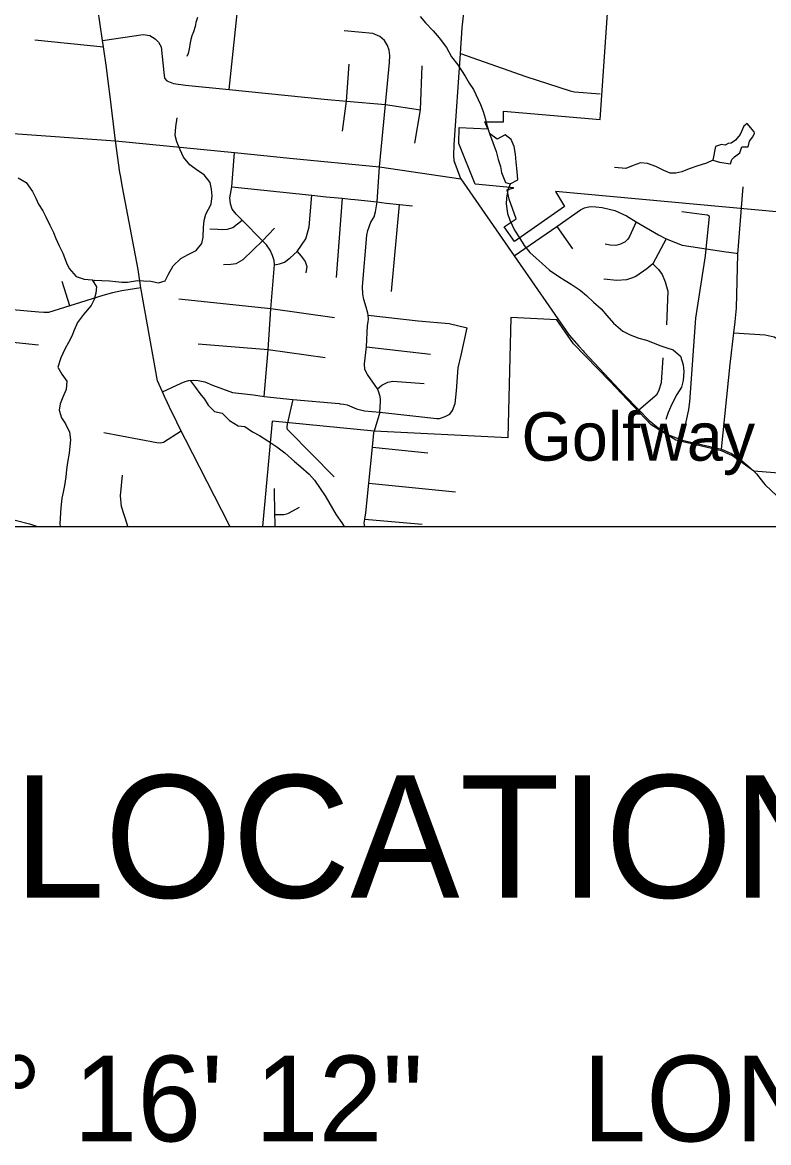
# Model space of a CAD drawing. Extents: x 0 to 69.5, y -4.5 to 22.
# Drawn here: x 4.384 to 5.602, y 13.194 to 15.023 of the extents above; entities that cross this region are included whole.
import ezdxf

# ---------------------------------------------------------------- set-up
doc = ezdxf.new("R2010")
doc.units = 0
for name, color, linetype in [('GM_X_City_Street', 7, 'Continuous'), ('GM_X_Corporation', 7, 'Continuous'), ('GM_X_County_Road', 7, 'Continuous'), ('GM_X_Minor_Lake', 7, 'Continuous'), ('GM_X_Minor_River', 7, 'Continuous'), ('GM_X_Township_ROW', 7, 'Continuous'), ('GM_X_Township_Subdivision', 7, 'Continuous'), ('GM_X_Unincorporated_Text', 7, 'Continuous'), ('GM_X_US_Route', 7, 'Continuous'), ('SH_Data', 7, 'Continuous')]:
    doc.layers.add(name, color=color, linetype=linetype)

msp = doc.modelspace()

# ---------------------------------------------------------------- linework, layer by layer
at = {"layer": 'GM_X_City_Street'}
for points in [[(4.8158, 14.3669), (4.8153, 14.3623), (4.8153, 14.3613), (4.8154, 14.3604), (4.8157, 14.3594), (4.816, 14.3588), (4.8185, 14.356), (4.8927, 14.2811)], [(4.9426, 14.2), (4.9417, 14.2051), (4.9428, 14.212), (4.9443, 14.222), (4.9492, 14.2708), (4.9551, 14.3294), (4.9574, 14.353), (4.9577, 14.3554)], [(4.9551, 14.3294), (5.0453, 14.3199)], [(4.9492, 14.2708), (5.0904, 14.2564)], [(5.5934, 14.2713), (5.5961, 14.2678), (5.6155, 14.2498), (5.6358, 14.2115), (5.6405, 14.2)], [(4.7969, 14.2), (4.7964, 14.2007), (4.7962, 14.2064), (4.7959, 14.2197), (4.7949, 14.2619)], [(4.7959, 14.2197), (4.8102, 14.2197), (4.8151, 14.2207), (4.8182, 14.2214), (4.825, 14.2254), (4.8359, 14.2316)], [(4.9428, 14.212), (5.0363, 14.2035)]]:
    msp.add_lwpolyline(points, dxfattribs=at)
at = {"layer": 'GM_X_Corporation'}
msp.add_line((4.7755, 14.2), (7.1307, 14.2), dxfattribs=at)
for points in [[(6.9956, 14.8531), (6.7125, 14.887), (6.701, 14.6468), (6.473, 14.6817), (6.4728, 14.6434), (5.9933, 14.679), (5.254, 14.7467), (5.2688, 14.7224), (5.187, 14.6653), (5.1701, 14.6893), (5.1899, 14.7022), (5.1782, 14.7342), (5.1751, 14.7498), (5.1856, 14.7529), (5.1229, 14.7587), (5.0962, 14.8253), (5.0967, 14.8513), (5.1434, 14.8494), (5.1387, 14.8608), (5.1692, 14.8604), (5.1692, 14.8783), (5.3269, 14.8644), (5.36, 15.3466)], [(6.9956, 14.8531), (6.7125, 14.887), (6.701, 14.6468), (6.473, 14.6817), (6.4728, 14.6434), (5.9933, 14.679), (5.9556, 14.2595), (5.5778, 14.2901), (5.5429, 14.3154), (5.5247, 14.3232), (5.4502, 14.341), (5.4099, 14.3661), (5.3427, 14.4372), (5.2834, 14.4983), (5.256, 14.5372), (5.1809, 14.5414), (5.1758, 14.3448), (4.9577, 14.3554), (4.7915, 14.3718), (4.7755, 14.2)]]:
    msp.add_lwpolyline(points, dxfattribs=at)
at = {"layer": 'GM_X_County_Road'}
for points in [[(5.0993, 14.7678), (5.0886, 14.7969), (5.0877, 14.8064), (5.0885, 14.8231), (5.0988, 14.9724), (5.1017, 15.0142), (5.1101, 15.0924)], [(4.0583, 14.9068), (4.0642, 14.9062), (4.1976, 14.8897), (4.2818, 14.8811), (4.2881, 14.8783), (4.2964, 14.8747), (4.3359, 14.8464), (4.3446, 14.8435), (4.3609, 14.8419), (4.5356, 14.8298)], [(4.5356, 14.8298), (4.7297, 14.8106), (4.8202, 14.8014), (4.9663, 14.7871), (5.0993, 14.7678)], [(5.0993, 14.7678), (5.1865, 14.6418), (5.2762, 14.5124), (5.2922, 14.4942), (5.2988, 14.4868)], [(5.2988, 14.4868), (5.3005, 14.4848), (5.3666, 14.4142), (5.39, 14.3902), (5.4068, 14.3731), (5.4213, 14.3611), (5.4388, 14.3493), (5.4588, 14.3415), (5.4609, 14.341), (5.525, 14.3259), (5.5412, 14.3193), (5.5527, 14.3119), (5.56, 14.306), (5.5714, 14.2962), (5.5823, 14.2858), (5.5934, 14.2713)], [(4.1028, 14.434), (4.1195, 14.4158), (4.1579, 14.3722), (4.1966, 14.328), (4.2251, 14.2968), (4.2366, 14.285), (4.2423, 14.2793), (4.2507, 14.2724), (4.2769, 14.2535), (4.3069, 14.2332), (4.3221, 14.2249), (4.3341, 14.2204), (4.3524, 14.2153), (4.3953, 14.2041), (4.4082, 14.2)]]:
    msp.add_lwpolyline(points, dxfattribs=at)
at = {"layer": 'GM_X_Minor_Lake'}
for points in [[(5.5107, 14.7981), (5.5218, 14.7946), (5.5395, 14.7919), (5.542, 14.7991), (5.5463, 14.8035), (5.5551, 14.8102), (5.558, 14.82), (5.5687, 14.8198), (5.5708, 14.8288), (5.5759, 14.8363), (5.579, 14.8419), (5.5783, 14.8442), (5.5668, 14.8581), (5.5614, 14.8537), (5.5554, 14.8402), (5.548, 14.8308), (5.5407, 14.8257), (5.5357, 14.825), (5.5311, 14.8225), (5.5247, 14.8238), (5.5151, 14.8202)], [(5.1462, 14.8416), (5.1569, 14.812), (5.1604, 14.799), (5.1639, 14.7875), (5.1659, 14.778), (5.172, 14.7618), (5.1796, 14.7594)], [(5.1796, 14.7594), (5.1926, 14.7659), (5.1914, 14.7796), (5.1895, 14.7945), (5.1883, 14.8078), (5.1864, 14.8201), (5.1817, 14.832), (5.1716, 14.8394), (5.1585, 14.8325), (5.1462, 14.8416)], [(5.5151, 14.8202), (5.5107, 14.7981)]]:
    msp.add_lwpolyline(points, dxfattribs=at)
at = {"layer": 'GM_X_Minor_River'}
for points in [[(4.6696, 15.0309), (4.6667, 15.0226), (4.6654, 15.0162), (4.6628, 15.0075), (4.6604, 15.0011), (4.6583, 14.995), (4.657, 14.9871), (4.6565, 14.9825), (4.6552, 14.9772), (4.6539, 14.9723), (4.6519, 14.9674)], [(5.0331, 15.0326), (5.0415, 15.0221), (5.0541, 15.0092), (5.0641, 14.9976), (5.0759, 14.9821), (5.0843, 14.967), (5.0946, 14.9535), (5.1063, 14.935), (5.1129, 14.9238), (5.1198, 14.9133), (5.1314, 14.8887), (5.1357, 14.8776), (5.1388, 14.8665), (5.142, 14.855), (5.1462, 14.8416)], [(4.4991, 14.6003), (4.502, 14.6021), (4.513, 14.6018), (4.5255, 14.6011), (4.5358, 14.6001), (4.5456, 14.5991), (4.5551, 14.5989), (4.5715, 14.6015), (4.581, 14.6009), (4.5931, 14.6006), (4.6056, 14.598), (4.6167, 14.6008), (4.6219, 14.6117), (4.6295, 14.6256), (4.6419, 14.6374), (4.6542, 14.644), (4.6673, 14.6505), (4.6767, 14.6617), (4.6789, 14.6723), (4.6792, 14.6879), (4.6803, 14.6993), (4.6832, 14.7098), (4.6916, 14.726), (4.6931, 14.74), (4.6922, 14.7507), (4.6902, 14.7618), (4.6802, 14.7742), (4.6693, 14.7809), (4.657, 14.7903), (4.6467, 14.8031), (4.6413, 14.815), (4.6355, 14.8281), (4.6327, 14.8385), (4.6338, 14.8525), (4.6361, 14.8673)], [(5.5107, 14.7981), (5.5003, 14.793), (5.4846, 14.7881), (5.472, 14.7838), (5.4601, 14.7792), (5.4505, 14.7767), (5.441, 14.777), (5.4305, 14.7814), (5.4178, 14.7878), (5.4042, 14.7927), (5.3928, 14.7937), (5.3806, 14.7895), (5.3687, 14.7844), (5.3501, 14.786)], [(4.3768, 14.7694), (4.3896, 14.7615), (4.4002, 14.7471), (4.4053, 14.736), (4.41, 14.7264), (4.4169, 14.7152), (4.422, 14.7055), (4.4285, 14.6917), (4.4343, 14.6801), (4.4383, 14.6702), (4.4437, 14.6582), (4.4495, 14.6463), (4.4555, 14.6306), (4.4599, 14.621), (4.4713, 14.6081), (4.4845, 14.604), (4.4974, 14.6029), (4.5047, 14.591), (4.5034, 14.5811), (4.5008, 14.5705), (4.496, 14.5607), (4.4835, 14.5462), (4.4733, 14.5328), (4.4681, 14.5207), (4.464, 14.5106), (4.4585, 14.5001), (4.4529, 14.4892), (4.4461, 14.4753), (4.4412, 14.4602), (4.4481, 14.4486), (4.4558, 14.437), (4.4551, 14.4237), (4.4495, 14.4113), (4.4454, 14.4), (4.4436, 14.3901), (4.4471, 14.3771), (4.4541, 14.3675), (4.4606, 14.354), (4.4618, 14.3414), (4.4612, 14.3308), (4.4598, 14.3194), (4.4571, 14.3046), (4.4553, 14.2929), (4.4543, 14.2811), (4.452, 14.2667), (4.4499, 14.2561), (4.4481, 14.2463), (4.4462, 14.2304), (4.4451, 14.2137), (4.4448, 14.2042), (4.4449, 14.2)], [(5.1805, 14.7599), (5.1763, 14.7496), (5.1737, 14.7359), (5.1731, 14.7265), (5.1757, 14.7112), (5.1793, 14.7001), (5.1868, 14.6839), (5.1949, 14.6712), (5.2026, 14.6588), (5.2118, 14.6472), (5.2222, 14.6378), (5.2319, 14.6292), (5.2442, 14.6186), (5.2595, 14.608), (5.2696, 14.6013), (5.2793, 14.5953), (5.2939, 14.5859), (5.3043, 14.5772), (5.3159, 14.5663), (5.3285, 14.5554), (5.3377, 14.5445), (5.3485, 14.532), (5.3637, 14.5187), (5.3757, 14.5128), (5.39, 14.5075), (5.4025, 14.5041), (5.4123, 14.5005), (5.4243, 14.4952), (5.4341, 14.4919), (5.4462, 14.4886), (5.4581, 14.478), (5.4623, 14.4639), (5.4636, 14.4528), (5.4625, 14.4384), (5.4595, 14.4274), (5.452, 14.4154), (5.4437, 14.3997), (5.438, 14.3858), (5.4339, 14.3744)], [(4.658, 14.4378), (4.6661, 14.4269), (4.6731, 14.4173), (4.6808, 14.4076), (4.6867, 14.3979), (4.6974, 14.3878), (4.7095, 14.3852), (4.7214, 14.3731), (4.736, 14.364), (4.7466, 14.3634), (4.7593, 14.3543), (4.7706, 14.3484), (4.784, 14.3397), (4.799, 14.3302), (4.8117, 14.32), (4.8277, 14.3059), (4.8381, 14.2973), (4.8519, 14.2855), (4.8604, 14.2758), (4.8699, 14.2619), (4.878, 14.2499), (4.8838, 14.2395), (4.89, 14.2291), (4.8959, 14.2191), (4.9051, 14.2059), (4.9086, 14.2)]]:
    msp.add_lwpolyline(points, dxfattribs=at)
at = {"layer": 'GM_X_Township_ROW'}
msp.add_lwpolyline([(5.5514, 14.6447), (5.5601, 14.7544)], dxfattribs=at)
at = {"layer": 'GM_X_Township_Subdivision'}
for points in [[(4.7213, 14.9134), (4.7368, 15.0634)], [(4.5144, 14.9937), (4.5806, 15.0034), (4.5916, 15.0014), (4.6001, 14.9964), (4.6058, 14.9909), (4.6098, 14.9829), (4.6143, 14.9412), (4.6153, 14.9319), (4.6193, 14.9277), (4.6303, 14.9232), (4.6496, 14.9204), (4.7213, 14.9134), (4.8763, 14.8977), (4.9125, 14.8942), (4.9763, 14.8887), (5.0335, 14.8802)], [(4.948, 14.5339), (4.9486, 14.5383), (4.948, 14.5448), (4.9477, 14.5482), (4.9445, 14.5578), (4.9411, 14.5708), (4.9394, 14.5792), (4.9386, 14.5918), (4.946, 14.6755), (4.9477, 14.6834), (4.9522, 14.697), (4.9577, 14.7057), (4.9601, 14.7136), (4.9629, 14.7298), (4.9636, 14.7466), (4.9663, 14.7871), (4.9763, 14.8887), (4.9828, 14.9574), (4.9835, 14.9691), (4.9823, 14.9779), (4.9798, 14.9851), (4.9748, 14.9936), (4.9673, 15.0001), (4.9558, 15.0046), (4.909, 15.0094)], [(4.4039, 14.9946), (4.5159, 14.9833)], [(5.0988, 14.9724), (5.2052, 14.9349), (5.2778, 14.9111), (5.285, 14.9094), (5.3266, 14.9065)], [(4.9062, 14.8455), (4.9125, 14.8942), (4.9168, 14.9549)], [(5.0241, 14.8259), (5.0335, 14.8802), (5.0364, 14.952)], [(4.778, 14.4122), (4.7846, 14.4883), (4.7893, 14.5551), (4.7949, 14.6269), (4.7948, 14.6341), (4.792, 14.6426), (4.7882, 14.6512), (4.7823, 14.6597), (4.7757, 14.6663), (4.7423, 14.7), (4.7327, 14.71), (4.7259, 14.7182), (4.7235, 14.7265), (4.722, 14.7368), (4.7257, 14.7543), (4.7297, 14.8106)], [(4.7257, 14.7543), (4.8558, 14.741), (4.8793, 14.7383), (4.9056, 14.7358), (4.919, 14.7346)], [(4.7949, 14.6269), (4.8031, 14.6288), (4.8116, 14.6317), (4.8207, 14.6384), (4.832, 14.649), (4.8462, 14.6696), (4.8487, 14.6772), (4.8517, 14.6892), (4.8558, 14.741)], [(4.9056, 14.7358), (4.8956, 14.6064)], [(4.919, 14.7346), (4.9262, 14.734), (4.9629, 14.7298), (4.9698, 14.729)], [(4.9698, 14.729), (4.978, 14.728), (4.999, 14.7254), (5.0206, 14.7234)], [(4.9862, 14.5837), (4.999, 14.7254)], [(5.1865, 14.6418), (5.2558, 14.6899), (5.2945, 14.7171), (5.3011, 14.7201), (5.3058, 14.7213), (5.3112, 14.7226)], [(5.3112, 14.7226), (5.32, 14.7219), (5.3302, 14.721), (5.3507, 14.7158), (5.37, 14.7072), (5.3858, 14.6971), (5.4218, 14.676), (5.4348, 14.6698), (5.4605, 14.6593), (5.4997, 14.6534), (5.5325, 14.6485), (5.5411, 14.6473), (5.5489, 14.6463), (5.5505, 14.6455), (5.5512, 14.6449), (5.5514, 14.6447)], [(5.4609, 14.341), (5.4694, 14.3808), (5.4714, 14.3907), (5.4731, 14.4032), (5.4832, 14.5398), (5.499, 14.6416), (5.4997, 14.6534), (5.5052, 14.706), (5.5018, 14.7085), (5.4927, 14.7092), (5.4604, 14.7136)], [(4.6894, 14.686), (4.7028, 14.6851), (4.7103, 14.6848), (4.7182, 14.6854), (4.7272, 14.6882), (4.7423, 14.7)], [(5.2558, 14.6899), (5.2816, 14.6534)], [(5.3858, 14.6971), (5.3746, 14.6735), (5.3718, 14.669), (5.3676, 14.6645), (5.36, 14.6608), (5.3524, 14.6588), (5.3434, 14.6592), (5.3348, 14.661)], [(4.7116, 14.6275), (4.7239, 14.628), (4.7326, 14.6291), (4.744, 14.6361), (4.7757, 14.6663), (4.7952, 14.6868)], [(5.4348, 14.6698), (5.4127, 14.6288), (5.4032, 14.6206), (5.3849, 14.6082), (5.378, 14.6052), (5.3697, 14.6025), (5.3541, 14.6013), (5.3326, 14.6035)], [(4.832, 14.649), (4.8388, 14.6411), (4.8454, 14.6326), (4.8478, 14.6244), (4.8465, 14.6139)], [(5.547, 14.5345), (5.5494, 14.5562), (5.5514, 14.6447)], [(5.4127, 14.6288), (5.4218, 14.6196), (5.4282, 14.6111), (5.4331, 14.5995), (5.4372, 14.5843), (5.4352, 14.5291)], [(4.4611, 14.5601), (4.4485, 14.6001)], [(4.5769, 14.5898), (4.5457, 14.5846), (4.5306, 14.5813), (4.5149, 14.5768), (4.4611, 14.5601), (4.426, 14.5494), (4.4187, 14.5494), (4.4102, 14.5498), (4.3675, 14.5534)], [(4.8929, 14.5405), (4.7893, 14.5551), (4.6387, 14.5711)], [(4.948, 14.5448), (5.0294, 14.5356), (5.0801, 14.5313), (5.1095, 14.5245)], [(4.4097, 14.496), (4.3628, 14.5007), (4.2815, 14.5075), (4.2152, 14.5138), (4.1302, 14.5211), (4.067, 14.5266), (4.0606, 14.5267), (4.0536, 14.5259), (4.0449, 14.5223), (4.033, 14.5098)], [(4.9024, 14.4004), (4.9077, 14.3994), (4.9135, 14.3983), (4.9291, 14.3918), (4.9422, 14.389), (4.9668, 14.3867), (5.0602, 14.3763), (5.0644, 14.3764), (5.074, 14.3794), (5.0815, 14.3832), (5.0858, 14.3891), (5.0899, 14.4005), (5.0923, 14.4215), (5.095, 14.4587), (5.0997, 14.4795), (5.1095, 14.5245)], [(4.9668, 14.3867), (4.9683, 14.4033), (4.9682, 14.4071), (4.9675, 14.4123), (4.9666, 14.4154), (4.9653, 14.4194), (4.9635, 14.4249), (4.9468, 14.4478), (4.9425, 14.4564), (4.9418, 14.4653), (4.9455, 14.4933), (4.9471, 14.5281), (4.948, 14.5339)], [(5.525, 14.3259), (5.5393, 14.4652), (5.545, 14.5162), (5.547, 14.5343), (5.547, 14.5345)], [(5.545, 14.5162), (5.5961, 14.5129), (5.6111, 14.5096), (5.6215, 14.5038), (5.6286, 14.494), (5.6354, 14.4771), (5.6429, 14.4654), (5.6507, 14.4615), (5.6608, 14.4589), (5.6803, 14.4563), (5.7698, 14.4494)], [(4.878, 14.4751), (4.7846, 14.4883), (4.6702, 14.4974)], [(4.9455, 14.4933), (5.05, 14.4811)], [(5.39, 14.3902), (5.4197, 14.416), (5.4234, 14.4231), (5.4269, 14.435), (5.4294, 14.4752)], [(4.6123, 14.4199), (4.6428, 14.4339), (4.6493, 14.4367), (4.6552, 14.4383), (4.6622, 14.4387), (4.6703, 14.4383), (4.6813, 14.4359), (4.6938, 14.4304), (4.7264, 14.4188), (4.7606, 14.4149), (4.778, 14.4122), (4.8252, 14.4072), (4.9008, 14.4007), (4.9024, 14.4004)], [(4.9635, 14.4249), (4.9701, 14.4308), (4.98, 14.4353), (4.9884, 14.437), (5.0392, 14.4331)], [(4.8252, 14.4072), (4.8158, 14.3669)], [(4.9668, 14.3867), (4.9577, 14.3554)], [(4.6428, 14.3557), (4.614, 14.3373), (4.6082, 14.336), (4.603, 14.3367), (4.5162, 14.3529)], [(4.5558, 14.2), (4.5545, 14.2035), (4.5454, 14.2324), (4.5434, 14.2501), (4.5471, 14.2836)]]:
    msp.add_lwpolyline(points, dxfattribs=at)
at = {"layer": 'GM_X_US_Route'}
for points in [[(4.5242, 14.9225), (4.5208, 14.9494), (4.5159, 14.9833), (4.5144, 14.9937), (4.4954, 15.1244), (4.4862, 15.1877), (4.4752, 15.2718), (4.4644, 15.355), (4.4625, 15.3694), (4.4601, 15.3824), (4.4536, 15.436), (4.4509, 15.4477), (4.4494, 15.4539)], [(4.5267, 14.9019), (4.5242, 14.9225)], [(4.5356, 14.8298), (4.5267, 14.9019)], [(4.5435, 14.7729), (4.5425, 14.7781), (4.5356, 14.8298)], [(4.5471, 14.7541), (4.5435, 14.7729)], [(4.7221, 14.2), (4.7203, 14.2037), (4.6497, 14.3417), (4.6428, 14.3557), (4.6284, 14.3852), (4.6266, 14.389), (4.6178, 14.4079), (4.6174, 14.4086), (4.6123, 14.4199), (4.6043, 14.4378), (4.5769, 14.5898), (4.5727, 14.6193), (4.5471, 14.7541)]]:
    msp.add_lwpolyline(points, dxfattribs=at)
at = {"layer": 'SH_Data'}
msp.add_line((2, 14.2), (8.8, 14.2), dxfattribs=at)

# ---------------------------------------------------------------- texts
at = {"layer": 'GM_X_Unincorporated_Text'}
msp.add_text('Golfway', height=0.07898, rotation=0, dxfattribs=at).set_placement((5.1984, 14.3074))
at = {"layer": 'SH_Data'}
for s, height, p in [('LOCATION MAP', 0.2, (4.3691, 13.5938)), ('LATITUDE:  39° 16\' 12"     LONGITUDE:  -84° 34\' 26"', 0.14, (3.071, 13.1959))]:
    msp.add_text(s, height=height, dxfattribs=at).set_placement(p)

doc.saveas('drawing.dxf')
